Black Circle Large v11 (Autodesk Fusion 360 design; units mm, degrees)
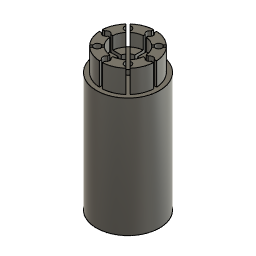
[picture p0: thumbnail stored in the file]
sketch "Sketch1" plane through (0, 0, 0) normal (0, 1, 0) x axis (1, 0, 0)
  circle C1 centre (0, 0) radius 22.5
  point P1 (0, 0)
  point P2 (0, 0)
  coincident P1 P2
  dimension "d1" diameter C1 = 45
extrude "Extrude1" new body sketch "Sketch1" along normal blind 85
hole "Hole1" HoleDepth 85 HoleDiameter 6.1 TipAngle 118
delete_face "DeleteFace1"
sketch "Sketch1" plane through (0, 85, 0) normal (0, 1, 0) x axis (-1, 0, 0)
  line L1 (-1.05, 19.3465) -> (-1.05, 0)
  line L2 (-1.05, -19.3465) -> (-1.05, 0)
  line L3 (1.05, -19.3465) -> (1.05, 0)
  line L4 (1.05, 19.3465) -> (1.05, 0)
  line L5 (-19.3465, 1.05) -> (0, 1.05)
  line L6 (19.3465, 1.05) -> (0, 1.05)
  line L7 (-19.3465, -1.05) -> (0, -1.05)
  line L8 (19.3465, -1.05) -> (0, -1.05)
  line L9 (19.5, 0) -> (0, 0)
  line L10 (-13.7886, 13.7886) -> (0, 0)
  line L11 (19.5, 0) -> (0, 0)
  line L12 (13.7886, -13.7886) -> (0, 0)
  line L13 (19.5, 0) -> (0, 0)
  line L14 (-13.7886, -13.7886) -> (0, 0)
  line L15 (19.5, 0) -> (0, 0)
  line L16 (13.7886, 13.7886) -> (0, 0)
  line L17 (19.5, 0) -> (0, 0)
  line L18 (-12.9376, 14.4225) -> (0.7425, 0.7425)
  line L19 (-14.4225, 12.9376) -> (-0.7425, -0.7425)
  line L20 (-14.4225, -12.9376) -> (-0.7425, 0.7425)
  line L21 (-12.9376, -14.4225) -> (0.7425, -0.7425)
  line L22 (12.9376, 14.4225) -> (-0.7425, 0.7425)
  line L23 (14.4225, 12.9376) -> (0.7425, -0.7425)
  line L24 (14.4225, -12.9376) -> (0.7425, 0.7425)
  line L25 (12.9376, -14.4225) -> (-0.7425, -0.7425)
  circle C1 centre (0, 0) radius 22.5
  circle C2 centre (0, 0) radius 19.375
  circle C3 centre (0, 0) radius 12
  circle C4 centre (0, 0) radius 1.05
  circle C5 centre (0, 0) radius 12
  circle C6 centre (0, 0) radius 6
  circle C7 centre (0, 0) radius 15.5
  circle C8 centre (0, 15.5) radius 2.45
  circle C9 centre (10.9602, 10.9602) radius 2.45
  circle C10 centre (15.5, 0) radius 2.45
  circle C11 centre (10.9602, -10.9602) radius 2.45
  circle C12 centre (0, -15.5) radius 2.45
  circle C13 centre (-10.9602, -10.9602) radius 2.45
  circle C14 centre (-15.5, 0) radius 2.45
  circle C15 centre (-10.9602, 10.9602) radius 2.45
  point P6 (-1.05, 0)
  point P7 (-1.05, 19.3465)
  point P8 (-1.05, -19.3465)
  point P9 (1.05, 0)
  point P10 (1.05, -19.3465)
  point P11 (1.05, 19.3465)
  point P12 (0, 1.05)
  point P13 (-19.3465, 1.05)
  point P14 (19.3465, 1.05)
  point P15 (0, -1.05)
  point P16 (-19.3465, -1.05)
  point P17 (19.3465, -1.05)
  point P3 (0, 0)
  point P18 (0, 0)
  point P20 (0, 0)
  point P27 (0, 0)
  point P33 (0.7425, 0.7425)
  point P34 (-12.9376, 14.4225)
  point P35 (-0.7425, -0.7425)
  point P36 (-14.4225, 12.9376)
  point P37 (-0.7425, 0.7425)
  point P38 (-14.4225, -12.9376)
  point P39 (0.7425, -0.7425)
  point P40 (-12.9376, -14.4225)
  point P41 (12.9376, 14.4225)
  point P42 (14.4225, 12.9376)
  point P43 (14.4225, -12.9376)
  point P44 (12.9376, -14.4225)
  point P45 (0, 0)
  point P47 (0, 15.5)
  point P48 (10.9602, 10.9602)
  point P49 (15.5, 0)
  point P50 (10.9602, -10.9602)
  point P51 (0, -15.5)
  point P52 (-10.9602, -10.9602)
  point P53 (-15.5, 0)
  point P54 (-10.9602, 10.9602)
  concentric C1 C2
  concentric C2 C3
  concentric C3 C4
  coincident C4 P6
  coincident C2 P7
  tangent C4 L1
  vertical L1
  coincident C2 P8
  tangent C4 L2
  coincident C4 P9
  coincident C2 P10
  tangent C4 L3
  parallel L2 L3
  coincident C2 P11
  tangent C4 L4
  coincident C4 P12
  coincident C2 P13
  tangent C4 L5
  perpendicular L1 L5
  coincident C2 P14
  tangent C4 L6
  coincident C4 P15
  coincident C2 P16
  tangent C4 L7
  parallel L6 L7
  coincident C2 P17
  tangent C4 L8
  horizontal L9
  coincident P3 P18
  concentric C4 C5
  horizontal L11
  horizontal L13
  horizontal L15
  coincident P20 P27
  horizontal L17
  coincident L16 P33
  coincident C4 P33
  coincident C2 P34
  tangent C4 L18
  coincident C4 P35
  coincident L14 P35
  coincident C2 P36
  tangent C4 L19
  coincident L10 P37
  coincident C4 P37
  coincident C2 P38
  tangent C4 L20
  coincident C4 P39
  coincident L12 P39
  coincident C2 P40
  tangent C4 L21
  coincident C2 P41
  tangent C4 L22
  coincident C2 P42
  tangent C4 L23
  coincident C2 P43
  parallel L12 L24
  coincident C2 P44
  perpendicular L21 L25
  coincident P18 P45
  concentric C3 C7
  coincident C7 P47
  coincident C7 P48
  coincident L16 P48
  coincident L11 P49
  coincident C7 P49
  coincident C7 P50
  coincident L12 P50
  coincident C7 P51
  coincident L14 P52
  coincident C7 P52
  coincident C7 P53
  coincident L10 P54
  coincident C7 P54
  dimension "d73" diameter C2 = 38.75
  dimension "d74" diameter C3 = 24
  dimension "d75" diameter C4 = 2.1
  dimension "d79" diameter C5 = 24
  dimension "d85" angle L10 L11 = 135
  dimension "d87" angle L14 L15 = 135
  dimension "d88" angle L16 L17 = 45
  dimension "d95" diameter C6 = 12
  dimension "d98" diameter C7 = 31
  dimension "d100" diameter C8 = 4.9
  dimension "d101" diameter C9 = 4.9
  dimension "d102" diameter C10 = 4.9
  dimension "d103" diameter C11 = 4.9
  dimension "d104" diameter C12 = 4.9
  dimension "d105" diameter C13 = 4.9
  dimension "d106" diameter C14 = 4.9
  dimension "d107" diameter C15 = 4.9
extrude "Extrude4" add sketch "Sketch1" profile of C3 L1 L2 L3 L4 L5 L6 L7 L8 C5 L18 L19 L20 L21 L22 L23 L24 L25 C6 along normal blind 7.25
extrude "Extrude5" add sketch "Sketch1" profile of C2 C3 L1 L2 L3 L4 L5 L6 L7 L8 C5 L18 L19 L20 L21 L22 L23 L24 L25 C7 C8 C9 C10 C11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 along normal blind 16.25
hole "Hole2" HoleDepth 85 HoleDiameter 5.1 TipAngle 180
extrude "Extrude2" add sketch "Sketch1" profile of C2 C3 L1 L2 L3 L4 L5 L6 L7 L8 C5 L18 L19 L20 L21 L22 L23 L24 L25 C7 C8 C9 C10 C11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 along normal blind 16.4
extrude "Extrude3" add sketch "Sketch1" profile of C3 L1 L2 L3 L4 L5 L6 L7 L8 C5 L18 L19 L20 L21 L22 L23 L24 L25 C6 along normal blind 7.4
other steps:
create_component "CreateComponent1"
create_component "CreateComponent5"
